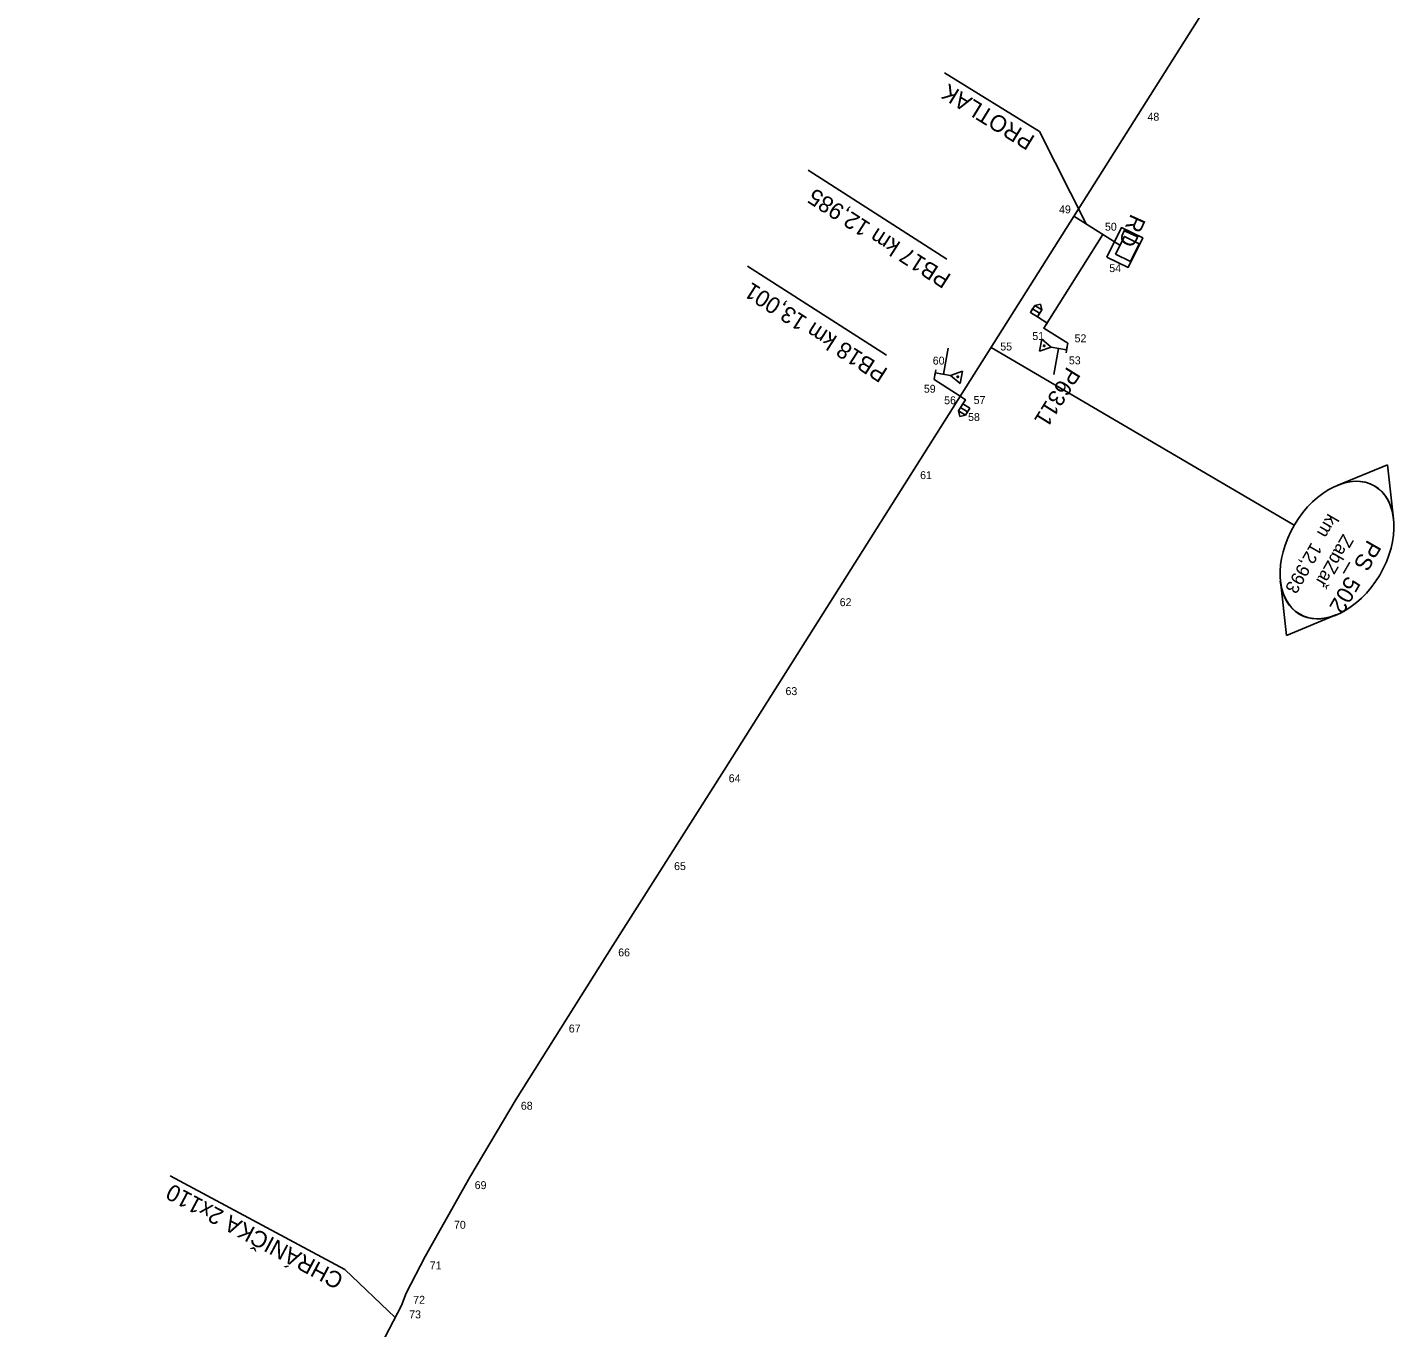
# Model space of a CAD drawing. Extents: x -743397 to -742769, y -1127804 to -1126284.
# Drawn here: x -743321.6 to -743113.4, y -1127244.4 to -1127047.4 of the extents above; entities that cross this region are included whole.
import ezdxf

# ---------------------------------------------------------------- set-up
doc = ezdxf.new("R2010")
doc.units = 0
for name, color, linetype in [('_Násyp', 7, 'Continuous'), ('_Zabezpečovací zařízení', 7, 'Continuous'), ('_Zabezpečovací zařízení_trasa', 7, 'Continuous'), ('bublina_fialová_čára_tenká', 7, 'Continuous'), ('bublina_růžová_230_čára_tučná', 7, 'Continuous'), ('křížky', 7, 'Continuous'), ('Nový stav', 7, 'Continuous'), ('Vrstva 60', 7, 'Continuous')]:
    doc.layers.add(name, color=color, linetype=linetype)

# ---------------------------------------------------------------- blocks, each defined once
blk = doc.blocks.new('POINT_DISPLAY')
blk.add_line((0, 0), (0, 0))

msp = doc.modelspace()

# ---------------------------------------------------------------- linework, layer by layer
for points in [[(-743157.95, -1127082.18), (-743155.73, -1127077.7), (-743152.5, -1127079.25), (-743154.72, -1127083.73)], [(-743156.61, -1127081.72), (-743155.27, -1127079.04), (-743153.03, -1127080.15), (-743154.37, -1127082.83)]]:
    msp.add_lwpolyline(points, close=True)
at = {"layer": '_Zabezpečovací zařízení'}
for p, q in [((-743168.87, -1127089.48), (-743169.53, -1127090.54)), ((-743169.2, -1127090.01), (-743168.14, -1127090.68)), ((-743168, -1127089.29), (-743168.87, -1127089.48)), ((-743167.81, -1127090.15), (-743168.87, -1127089.48)), ((-743167.81, -1127090.15), (-743168, -1127089.29)), ((-743169.53, -1127090.54), (-743168.47, -1127091.21)), ((-743168.47, -1127091.21), (-743167.81, -1127090.15)), ((-743182.71, -1127099.93), (-743182.01, -1127095.99)), ((-743168.14, -1127096.45), (-743167.81, -1127094.59)), ((-743166.36, -1127095.8), (-743168.14, -1127096.45)), ((-743167.81, -1127094.59), (-743166.36, -1127095.8)), ((-743166.36, -1127095.8), (-743164.04, -1127096.22)), ((-743165.27, -1127096), (-743165.96, -1127099.94)), ((-743164.12, -1127096.68), (-743163.95, -1127095.75)), ((-743183.86, -1127099.25), (-743184.02, -1127100.18)), ((-743181.61, -1127100.12), (-743183.94, -1127099.71)), ((-743181.61, -1127100.12), (-743179.84, -1127099.48)), ((-743180.17, -1127101.34), (-743181.61, -1127100.12)), ((-743179.84, -1127099.48), (-743180.17, -1127101.34)), ((-743179.77, -1127104.42), (-743180.44, -1127105.47)), ((-743178.72, -1127105.08), (-743179.77, -1127104.42)), ((-743180.44, -1127105.47), (-743179.38, -1127106.14)), ((-743180.44, -1127105.47), (-743180.24, -1127106.34)), ((-743180.24, -1127106.34), (-743179.38, -1127106.14)), ((-743179.05, -1127105.61), (-743180.11, -1127104.94)), ((-743179.38, -1127106.14), (-743178.72, -1127105.08))]:
    msp.add_line(p, q, dxfattribs=at)
for points in [[(-743168.47, -1127091.21), (-743168.14, -1127090.68), (-743169.2, -1127090.01), (-743169.53, -1127090.54), (-743168.47, -1127091.21)], [(-743179.77, -1127104.42), (-743180.11, -1127104.94), (-743179.05, -1127105.61), (-743178.72, -1127105.08), (-743179.77, -1127104.42)]]:
    msp.add_lwpolyline(points, dxfattribs=at)
for centre, start, end in [((-743167.44, -1127095.61), 79.9608, 259.9608), ((-743167.44, -1127095.61), 259.9608, 79.9608), ((-743180.54, -1127100.31), 79.9608, 259.9608), ((-743180.54, -1127100.31), 259.9608, 79.9608)]:
    msp.add_arc(centre, 0.118, start, end, dxfattribs=at)
at = {"layer": '_Zabezpečovací zařízení_trasa'}
msp.add_line((-743155.94, -1127080.38), (-743162.93, -1127075.97), dxfattribs=at)
for points in [[(-743125.94, -1127017.38), (-743152.6, -1127059.61), (-743175.02, -1127095.12), (-743199.16, -1127133.35), (-743215.97, -1127159.94), (-743232.82, -1127186.51), (-743247.46, -1127209.81), (-743254.52, -1127221.64), (-743261.3, -1127233.69), (-743264.16, -1127239.2), (-743264.86, -1127241.11), (-743267.34, -1127245.82), (-743268.29, -1127247.16), (-743271.71, -1127253.75), (-743281.12, -1127274.2), (-743291.92, -1127301.42), (-743296.72, -1127315.22), (-743301.12, -1127329.13), (-743306.79, -1127349.51), (-743311.54, -1127370.06), (-743315.69, -1127392.87), (-743318.79, -1127415.84), (-743321.57, -1127442.6)], [(-743164.04, -1127096.19), (-743163.86, -1127095.23), (-743167.49, -1127092.94), (-743158.53, -1127078.74)], [(-743168.47, -1127091.21), (-743166.88, -1127092.21)], [(-743183.94, -1127099.73), (-743184.12, -1127100.71), (-743180.17, -1127103.27)], [(-743180.54, -1127103.04), (-743180.54, -1127103.04)], [(-743179.77, -1127104.42), (-743179.37, -1127103.78), (-743180.17, -1127103.27)]]:
    msp.add_lwpolyline(points, dxfattribs=at)
at = {"layer": 'bublina_fialová_čára_tenká'}
msp.add_line((-743129.51, -1127122.8), (-743175.48, -1127095.85), dxfattribs=at)
at = {"layer": 'bublina_růžová_230_čára_tučná'}
for p, q in [((-743115.4, -1127113.65), (-743123.03, -1127116.79)), ((-743115.4, -1127113.65), (-743123.03, -1127116.79)), ((-743114.46, -1127121.85), (-743115.4, -1127113.65)), ((-743114.46, -1127121.85), (-743115.4, -1127113.65)), ((-743131.63, -1127131.3), (-743130.69, -1127139.51)), ((-743131.63, -1127131.3), (-743130.69, -1127139.51)), ((-743130.69, -1127139.51), (-743123.06, -1127136.36)), ((-743130.69, -1127139.51), (-743123.06, -1127136.36))]:
    msp.add_line(p, q, dxfattribs=at)
msp.add_ellipse((-743123.03, -1127126.57), major_axis=(-5.72, -9.69), ratio=0.666667, dxfattribs=at)
for centre, major_axis in [((-743123.03, -1127126.57), (5.72, 9.69)), ((-743123.07, -1127126.59), (-5.72, -9.69))]:
    msp.add_ellipse(centre, major_axis=major_axis, ratio=0.666473, start_param=5.557317, end_param=7.009053, dxfattribs=at)
at = {"layer": 'Nový stav'}
for p, q in [((-743168.13, -1127063.11), (-743182.57, -1127054.25)), ((-743168.13, -1127063.11), (-743182.57, -1127054.25)), ((-743161.07, -1127077.14), (-743168.13, -1127063.11)), ((-743161.07, -1127077.14), (-743168.13, -1127063.11)), ((-743182.17, -1127082.46), (-743203.23, -1127068.99)), ((-743182.17, -1127082.46), (-743203.23, -1127068.99)), ((-743191.34, -1127097.01), (-743212.4, -1127083.54)), ((-743191.34, -1127097.01), (-743212.4, -1127083.54)), ((-743273.44, -1127235.62), (-743299.92, -1127221.46)), ((-743273.44, -1127235.62), (-743299.92, -1127221.46)), ((-743265.82, -1127242.93), (-743273.44, -1127235.62)), ((-743265.82, -1127242.93), (-743273.44, -1127235.62))]:
    msp.add_line(p, q, dxfattribs=at)
at = {"layer": 'Vrstva 60'}
for p, q in [((-743152.6, -1127059.61), (-743152.6, -1127059.61)), ((-743162.93, -1127075.97), (-743162.93, -1127075.97)), ((-743158.53, -1127078.75), (-743158.53, -1127078.75)), ((-743155.94, -1127080.38), (-743155.94, -1127080.38)), ((-743167.49, -1127092.94), (-743167.49, -1127092.94)), ((-743175.02, -1127095.12), (-743175.02, -1127095.12)), ((-743164.04, -1127096.22), (-743164.04, -1127096.22)), ((-743163.86, -1127095.23), (-743163.86, -1127095.23)), ((-743183.94, -1127099.73), (-743183.94, -1127099.73)), ((-743184.12, -1127100.71), (-743184.12, -1127100.71)), ((-743180.17, -1127103.27), (-743180.17, -1127103.27)), ((-743179.77, -1127104.42), (-743179.77, -1127104.42)), ((-743179.37, -1127103.78), (-743179.37, -1127103.78)), ((-743187.09, -1127114.23), (-743187.09, -1127114.23)), ((-743199.16, -1127133.35), (-743199.16, -1127133.35)), ((-743207.57, -1127146.64), (-743207.57, -1127146.64)), ((-743215.97, -1127159.94), (-743215.97, -1127159.94)), ((-743224.4, -1127173.23), (-743224.4, -1127173.23)), ((-743232.82, -1127186.52), (-743232.82, -1127186.52)), ((-743240.14, -1127198.16), (-743240.14, -1127198.16)), ((-743247.46, -1127209.81), (-743247.46, -1127209.81)), ((-743254.52, -1127221.64), (-743254.52, -1127221.64)), ((-743257.91, -1127227.67), (-743257.91, -1127227.67)), ((-743261.3, -1127233.69), (-743261.3, -1127233.69)), ((-743264.16, -1127239.2), (-743264.16, -1127239.2)), ((-743264.86, -1127241.11), (-743264.86, -1127241.11))]:
    msp.add_line(p, q, dxfattribs=at)

# ---------------------------------------------------------------- block references
at = {"layer": 'křížky', "xscale": 10, "yscale": 10, "rotation": 61.14491455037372}
for p in [(-743152.6, -1127059.61), (-743162.93, -1127075.97), (-743158.26, -1127079.23), (-743155.94, -1127080.38), (-743167.49, -1127092.94), (-743175.02, -1127095.12), (-743164.04, -1127096.22), (-743163.86, -1127095.23), (-743183.94, -1127099.73), (-743184.12, -1127100.71), (-743180.17, -1127103.27), (-743179.77, -1127104.42), (-743179.37, -1127103.78), (-743187.09, -1127114.23), (-743199.16, -1127133.35), (-743207.57, -1127146.64), (-743215.97, -1127159.94), (-743224.39, -1127173.23), (-743232.82, -1127186.52), (-743240.14, -1127198.16), (-743247.46, -1127209.81), (-743254.52, -1127221.64), (-743257.91, -1127227.67), (-743261.3, -1127233.69), (-743264.16, -1127239.2), (-743264.86, -1127241.11)]:
    msp.add_blockref('POINT_DISPLAY', p, dxfattribs=at)

# ---------------------------------------------------------------- texts
msp.add_text('RD', height=2.5, rotation=245.8595).set_placement((-743154.25, -1127075.5))
at = {"layer": '_Násyp'}
for s, height, p in [('km  12,993', 2, (-743124.39, -1127120.92)), ('ZabZař', 2, (-743122.12, -1127124.02)), ('PS_502', 2.5, (-743118.38, -1127124.89))]:
    msp.add_text(s, height=height, rotation=240.1217, dxfattribs=at).set_placement(p)
at = {"layer": 'Nový stav'}
for s, rotation, p in [('PROTLAK', 148.4464, (-743168.67, -1127063.95)), ('PROTLAK', 148.4464, (-743168.67, -1127063.95)), ('PB17 km 12,985', 147.395, (-743181.38, -1127084.94)), ('PB17 km 12,985', 147.395, (-743181.38, -1127084.94)), ('PB18 km 13,001', 147.395, (-743190.98, -1127099.21)), ('PB18 km 13,001', 147.395, (-743190.98, -1127099.21)), ('P6311', 238, (-743163.93, -1127098.65)), ('P6311', 238, (-743163.93, -1127098.65)), ('CHRÁNIČKA 2x110', 151.8668, (-743273.44, -1127236.57)), ('CHRÁNIČKA 2x110', 151.8668, (-743273.44, -1127236.57))]:
    msp.add_text(s, height=2.5, rotation=rotation, dxfattribs=at).set_placement(p)
at = {"layer": 'Vrstva 60'}
for s, p in [('48', (-743151.77, -1127061.49)), ('49', (-743165.18, -1127075.53)), ('50', (-743158.22, -1127078.16)), ('54', (-743157.56, -1127084.44)), ('51', (-743169.23, -1127094.73)), ('52', (-743162.82, -1127095.08)), ('55', (-743174.09, -1127096.32)), ('60', (-743184.32, -1127098.46)), ('53', (-743163.69, -1127098.42)), ('59', (-743185.67, -1127102.72)), ('56', (-743182.6, -1127104.47)), ('57', (-743178.13, -1127104.44)), ('58', (-743178.97, -1127107.01)), ('61', (-743186.24, -1127115.82)), ('62', (-743198.43, -1127135.08)), ('63', (-743206.65, -1127148.56)), ('64', (-743215.26, -1127161.77)), ('65', (-743223.54, -1127175.09)), ('66', (-743232.01, -1127188.17)), ('67', (-743239.5, -1127199.71)), ('68', (-743246.77, -1127211.41)), ('69', (-743253.77, -1127223.45)), ('70', (-743256.91, -1127229.46)), ('71', (-743260.59, -1127235.62)), ('72', (-743263.09, -1127240.83)), ('73', (-743263.7, -1127243.04))]:
    msp.add_text(s, height=1.2, dxfattribs=at).set_placement(p)

doc.saveas('drawing.dxf')
